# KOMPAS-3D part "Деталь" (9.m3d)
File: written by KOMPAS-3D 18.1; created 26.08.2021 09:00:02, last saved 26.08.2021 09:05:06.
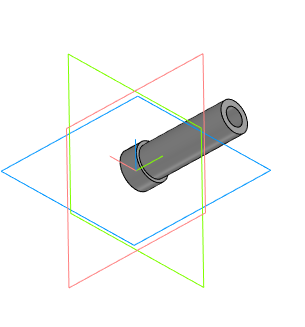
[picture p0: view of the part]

Document properties: Автор: 111; Полное имя файла: C:\Users\admin\Desktop\ffb\9.m3d

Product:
- Part/product: Деталь
    Масса: 0.0158448
    source file: ..\9.cdw, 9.cdw

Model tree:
1. Эскиз:1
2. Элемент выдавливания:1
     Расстояние 1 = 6
3. Эскиз:2  (with: Элемент выдавливания:1)
4. Элемент выдавливания:3
     Расстояние 1 = 30
5. Эскиз:3  (with: Элемент выдавливания:3)
6. Элемент выдавливания:4
     Расстояние 2 = 36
